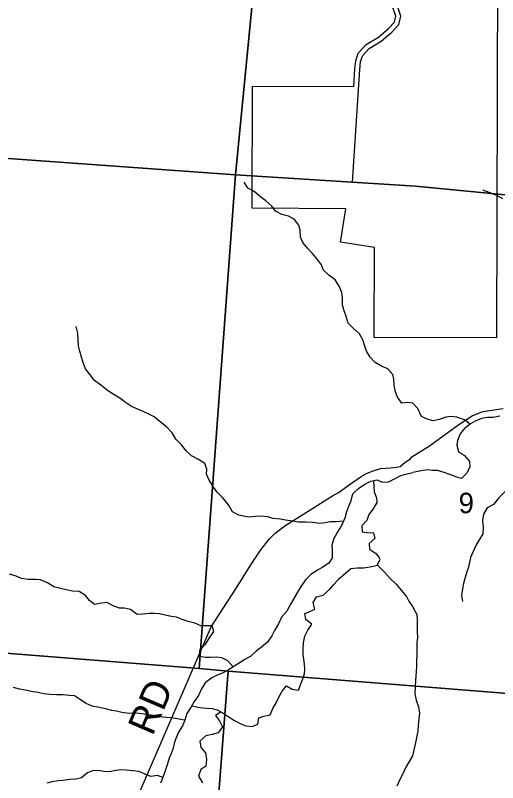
# Model space of a CAD drawing. Extents: x 0 to 34, y 0 to 22.
# Drawn here: x 27.839 to 28.825, y 17.514 to 19.082 of the extents above; entities that cross this region are included whole.
import ezdxf

# ---------------------------------------------------------------- set-up
doc = ezdxf.new("R2010")
doc.units = 0
for name, color, linetype in [('GM_X_City_Street', 7, 'Continuous'), ('GM_X_Corporation', 7, 'Continuous'), ('GM_X_County_Road', 7, 'Continuous'), ('GM_X_County_Road_Text', 7, 'Continuous'), ('GM_X_Minor_River', 7, 'Continuous'), ('GM_X_Section_Text', 7, 'Continuous')]:
    doc.layers.add(name, color=color, linetype=linetype)

msp = doc.modelspace()

# ---------------------------------------------------------------- linework, layer by layer
at = {"layer": 'GM_X_City_Street'}
msp.add_lwpolyline([(28.5283, 18.7412), (28.5427, 18.9719), (28.5446, 18.9871), (28.5485, 18.9999), (28.5622, 19.0147), (28.5869, 19.0297), (28.6086, 19.0482), (28.6227, 19.0634), (28.6265, 19.0804), (28.6183, 19.1051)], dxfattribs=at)
at = {"layer": 'GM_X_Corporation'}
for points in [[(27.4311, 19.8373), (28.3876, 19.7694), (28.2889, 18.7562), (27.2938, 18.8276), (27.3834, 19.8411)], [(28.4917, 19.7627), (29.3585, 19.6871), (29.2972, 18.6715), (28.6566, 18.7331), (28.2889, 18.7562), (28.3876, 19.7694)], [(27.2938, 18.8276), (28.2889, 18.7562), (28.2146, 17.7472), (27.2101, 17.8272)], [(28.2889, 18.7562), (28.6566, 18.7331), (29.2972, 18.6715), (29.263, 17.6631), (28.2741, 17.7417), (28.2146, 17.7472)], [(27.1442, 17.8319), (27.2101, 17.8272), (28.2146, 17.7472), (28.2741, 17.7417), (28.199, 16.7653), (27.1145, 16.8163), (27.1132, 17.3107)], [(28.2741, 17.7417), (29.263, 17.6631), (29.176, 16.6858), (28.199, 16.7653)]]:
    msp.add_lwpolyline(points, close=True, dxfattribs=at)
msp.add_lwpolyline([(28.8245, 19.173), (28.8221, 18.423), (28.5721, 18.4238), (28.5727, 18.6075), (28.5037, 18.6184), (28.5146, 18.6872), (28.3229, 18.6879), (28.3237, 18.9379), (28.5308, 18.9372), (28.533, 18.9733), (28.5351, 18.9896), (28.5398, 19.0053), (28.5559, 19.0226), (28.5811, 19.038), (28.6018, 19.0556), (28.6138, 19.0685), (28.6165, 19.0805), (28.6091, 19.1027)], dxfattribs=at)
at = {"layer": 'GM_X_County_Road'}
msp.add_lwpolyline([(27.9956, 17.2684), (28.2389, 17.8323), (28.2894, 17.91), (28.3217, 17.9615), (28.3409, 17.9902), (28.3576, 18.0116), (28.3691, 18.0235), (28.3899, 18.0387), (28.4873, 18.1004), (28.5005, 18.1078), (28.5191, 18.1217), (28.5457, 18.1395), (28.5577, 18.1469), (28.572, 18.1519), (28.5859, 18.1558), (28.6056, 18.1577), (28.618, 18.1588), (28.6257, 18.1604), (28.6354, 18.1689), (28.6457, 18.1754), (28.6492, 18.1803), (28.6854, 18.2027), (28.7455, 18.2461), (28.7723, 18.2641), (28.7943, 18.2729), (28.8356, 18.2786)], dxfattribs=at)
at = {"layer": 'GM_X_Minor_River'}
for points in [[(28.6514, 18.2895), (28.6404, 18.2907), (28.6291, 18.2896), (28.6201, 18.3022), (28.6152, 18.3151), (28.6134, 18.3269), (28.6124, 18.3387), (28.6102, 18.3485), (28.6004, 18.36), (28.5872, 18.3654), (28.5744, 18.3727), (28.5639, 18.3837), (28.5564, 18.3959), (28.5523, 18.4081), (28.549, 18.4191), (28.5426, 18.4317), (28.531, 18.4416), (28.5189, 18.4534), (28.5149, 18.4671), (28.51, 18.4804), (28.5078, 18.4899), (28.5076, 18.5043), (28.5061, 18.5161), (28.5005, 18.5287), (28.4927, 18.5416), (28.4799, 18.5516), (28.4682, 18.5619), (28.4645, 18.5725), (28.4566, 18.5836), (28.4461, 18.5958), (28.4364, 18.6065), (28.4262, 18.6183), (28.4217, 18.6289), (28.4211, 18.643), (28.4181, 18.6536), (28.4088, 18.6658), (28.3974, 18.672), (28.3835, 18.6755), (28.371, 18.682), (28.3631, 18.6923), (28.3511, 18.7034), (28.341, 18.7106), (28.327, 18.7225), (28.3138, 18.729), (28.3067, 18.7412)], [(28.8354, 18.7071), (28.8214, 18.7147), (28.8075, 18.7205), (28.7946, 18.7247)], [(28.5103, 18.0484), (28.495, 18.0474), (28.4825, 18.0471), (28.473, 18.0449), (28.4609, 18.0435), (28.4473, 18.0455), (28.4329, 18.0463), (28.4178, 18.0464), (28.4061, 18.0488), (28.3913, 18.0504), (28.3807, 18.0527), (28.3649, 18.054), (28.355, 18.0575), (28.3418, 18.0587), (28.3293, 18.058), (28.3157, 18.057), (28.3055, 18.0589), (28.2957, 18.0609), (28.2828, 18.0678), (28.2746, 18.0819), (28.2626, 18.0968), (28.251, 18.1086), (28.2435, 18.1196), (28.2348, 18.1322), (28.23, 18.1444), (28.2301, 18.1546), (28.2264, 18.1664), (28.2132, 18.1745), (28.1992, 18.1821), (28.1891, 18.1913), (28.1786, 18.2043), (28.1673, 18.2161), (28.1598, 18.2287), (28.1478, 18.2413), (28.135, 18.2516), (28.123, 18.2619), (28.112, 18.2673), (28.1, 18.2727), (28.0762, 18.2831), (28.0638, 18.2911), (28.0525, 18.2999), (28.0389, 18.3084), (28.0276, 18.3156), (28.014, 18.3264), (28.0005, 18.3363), (27.9896, 18.3504), (27.9825, 18.3599), (27.9773, 18.3729), (27.9743, 18.3839), (27.9706, 18.3961), (27.9684, 18.4067), (27.9674, 18.4196), (27.9667, 18.4325), (27.9634, 18.4462)], [(28.7683, 18.2468), (28.7567, 18.2557), (28.7415, 18.2611), (28.7287, 18.2622), (28.7185, 18.2608), (28.7052, 18.2566), (28.6927, 18.2533), (28.6806, 18.2567), (28.6689, 18.2621), (28.6617, 18.2791), (28.6514, 18.2895)], [(28.829, 18.2634), (28.8157, 18.2604), (28.804, 18.2605), (28.7919, 18.2582), (28.779, 18.253), (28.7695, 18.2477), (28.7562, 18.2375), (28.7482, 18.2273), (28.7425, 18.2133), (28.7413, 18.2038), (28.7447, 18.1909), (28.7568, 18.1825), (28.767, 18.1707), (28.7677, 18.1597), (28.7616, 18.1465), (28.751, 18.1359), (28.7411, 18.1386), (28.7268, 18.1439), (28.7154, 18.1481), (28.7014, 18.152), (28.6916, 18.152), (28.6818, 18.1532), (28.6719, 18.1521), (28.6511, 18.1477)], [(28.9456, 18.1756), (28.9327, 18.1713), (28.9259, 18.1577), (28.9164, 18.1543), (28.9073, 18.1433), (28.8955, 18.1346), (28.8872, 18.1248), (28.8739, 18.1207), (28.8603, 18.1166), (28.8493, 18.1117), (28.8387, 18.1075), (28.8261, 18.0954), (28.8159, 18.0826), (28.8034, 18.0754), (28.7957, 18.0629), (28.7934, 18.0497), (28.7949, 18.0356), (28.7941, 18.0227), (28.7872, 18.0102), (28.78, 17.9985), (28.7693, 17.9742)], [(28.4869, 17.9747), (28.487, 17.9902), (28.4867, 18.0004), (28.4906, 18.0137), (28.4963, 18.0235), (28.5028, 18.0341), (28.5086, 18.0443), (28.5132, 18.0553), (28.5167, 18.0685), (28.5206, 18.0791), (28.5244, 18.0889), (28.5287, 18.1045), (28.5401, 18.1154), (28.5534, 18.1244), (28.5652, 18.1304), (28.5781, 18.1333), (28.5886, 18.1283), (28.6019, 18.1286), (28.614, 18.135), (28.6269, 18.1417), (28.6372, 18.1447), (28.6511, 18.1477)], [(28.571, 18.1317), (28.5719, 18.1186), (28.5722, 18.1083), (28.5771, 18.0965), (28.5777, 18.0863), (28.5701, 18.0738), (28.5613, 18.0621), (28.5574, 18.05), (28.5468, 18.0387), (28.5478, 18.0266), (28.5576, 18.025), (28.5709, 18.0249), (28.5738, 18.0128), (28.5624, 18.003), (28.5627, 17.9912), (28.5751, 17.9828), (28.5825, 17.9745)], [(28.4869, 17.9747), (28.4795, 17.9627), (28.4658, 17.954), (28.4563, 17.948), (28.443, 17.9397), (28.432, 17.9284), (28.4233, 17.9159), (28.4157, 17.9034), (28.4081, 17.8905), (28.4008, 17.8777), (28.394, 17.8644), (28.383, 17.8524), (28.3769, 17.8387), (28.3685, 17.8251), (28.3631, 17.8141), (28.354, 17.8009), (28.3419, 17.7911), (28.332, 17.7832), (28.3202, 17.7726), (28.3081, 17.7658), (28.2982, 17.7594), (28.2854, 17.7511), (28.2759, 17.7455), (28.2626, 17.738), (28.2531, 17.7342), (28.2403, 17.7282), (28.227, 17.718), (28.2197, 17.7055), (28.2133, 17.6923), (28.2045, 17.6802), (28.1977, 17.6673), (28.1897, 17.6552), (28.1851, 17.642), (28.1805, 17.6302), (28.1725, 17.6174), (28.1668, 17.6041), (28.1633, 17.5943), (28.1618, 17.5848), (28.1584, 17.575), (28.1534, 17.5644), (28.1503, 17.5526), (28.1461, 17.5405), (28.1412, 17.5265), (28.1354, 17.5133)], [(28.1998, 17.6713), (28.2162, 17.6673), (28.2306, 17.6664), (28.2412, 17.6656), (28.2517, 17.6629), (28.2616, 17.6576), (28.274, 17.6492), (28.2872, 17.6412), (28.3001, 17.6343), (28.3099, 17.6301), (28.3227, 17.6289), (28.3345, 17.6334), (28.3364, 17.6463), (28.3466, 17.6497), (28.3595, 17.6527), (28.3652, 17.6659), (28.3725, 17.6788), (28.3774, 17.6886), (28.3843, 17.7007), (28.3934, 17.7121), (28.4047, 17.7048), (28.4176, 17.7029), (28.4222, 17.7161), (28.4264, 17.726), (28.4298, 17.7362), (28.4306, 17.746), (28.4299, 17.7559), (28.4288, 17.7661), (28.4273, 17.776), (28.4274, 17.787), (28.4278, 17.7999), (28.4305, 17.8131), (28.437, 17.8256), (28.4449, 17.8381), (28.4329, 17.8472), (28.4303, 17.8598), (28.4397, 17.8631), (28.4511, 17.8684), (28.4478, 17.8821), (28.4546, 17.8938), (28.4679, 17.8971), (28.4819, 17.9092), (28.4903, 17.9194), (28.5005, 17.9311), (28.5134, 17.9421), (28.5244, 17.9515), (28.5377, 17.953), (28.5505, 17.9529), (28.5642, 17.9552), (28.5782, 17.9585), (28.5846, 17.9702), (28.5825, 17.9745)], [(28.7693, 17.9742), (28.7652, 17.9548), (28.7614, 17.9446), (28.7583, 17.9336), (28.7552, 17.9211), (28.7525, 17.9105), (28.751, 17.8965), (28.7528, 17.8844)], [(28.5784, 17.959), (28.594, 17.9437), (28.6053, 17.9311), (28.6174, 17.9197), (28.6275, 17.9075), (28.6381, 17.8946), (28.6433, 17.8851), (28.6508, 17.874)], [(28.2844, 17.7506), (28.2733, 17.7633), (28.2612, 17.7694), (28.2491, 17.7702), (28.2381, 17.7695), (28.2279, 17.7699), (28.2151, 17.7719), (28.2163, 17.7851), (28.2273, 17.7972), (28.2356, 17.8097), (28.2444, 17.8229), (28.241, 17.8347), (28.2183, 17.8348), (28.2055, 17.8402), (28.1923, 17.8432), (28.1802, 17.8478), (28.1685, 17.852), (28.1579, 17.8536), (28.1477, 17.8559), (28.1337, 17.859), (28.1231, 17.8598), (28.1125, 17.8595), (28.0989, 17.8584), (28.0879, 17.858), (28.0743, 17.8679), (28.0618, 17.871), (28.0516, 17.8707), (28.0388, 17.8757), (28.0263, 17.8825), (28.0112, 17.8799), (28.0006, 17.8785), (27.9908, 17.8861), (27.9825, 17.8967), (27.9693, 17.9044), (27.956, 17.9056), (27.9428, 17.9083), (27.9311, 17.9106), (27.9175, 17.9144), (27.905, 17.9224), (27.8903, 17.9285), (27.8801, 17.9293), (27.865, 17.9294), (27.8514, 17.9314), (27.8408, 17.9363), (27.8272, 17.9402)], [(28.6508, 17.874), (28.6597, 17.8575), (28.6604, 17.8473), (28.6604, 17.8332), (28.6599, 17.8238), (28.6606, 17.8101), (28.6598, 17.8003), (28.6598, 17.7859), (28.6593, 17.7745), (28.6585, 17.7646), (28.6585, 17.7518), (28.6581, 17.7415), (28.6573, 17.732), (28.6569, 17.7226), (28.6564, 17.7093), (28.6556, 17.6953), (28.6582, 17.6824), (28.663, 17.6687), (28.6649, 17.6562), (28.6637, 17.6441), (28.6621, 17.6316), (28.6613, 17.6191), (28.659, 17.6054), (28.6563, 17.5925), (28.6503, 17.5689)], [(28.185, 17.6418), (28.1696, 17.6447), (28.1579, 17.6466), (28.1473, 17.647), (28.1333, 17.6486), (28.1208, 17.6513), (28.1072, 17.6536), (28.0921, 17.6552), (28.0819, 17.656), (28.0713, 17.6557), (28.0565, 17.6576), (28.0459, 17.6599), (28.0361, 17.6615), (28.0236, 17.6646), (28.01, 17.6677), (27.9957, 17.6704), (27.984, 17.6761), (27.9722, 17.6834), (27.9602, 17.6914), (27.95, 17.6925), (27.9363, 17.6937), (27.9231, 17.6938), (27.9099, 17.6942), (27.8974, 17.6958), (27.8857, 17.6981), (27.8755, 17.6996), (27.8588, 17.7031), (27.8475, 17.7054), (27.835, 17.7085)], [(28.2594, 17.6588), (28.2483, 17.6512), (28.2562, 17.6402), (28.2626, 17.628), (28.2538, 17.6159), (28.241, 17.6126), (28.2281, 17.6096), (28.2159, 17.599), (28.2178, 17.5861), (28.2276, 17.5747), (28.2294, 17.5614), (28.2286, 17.5478), (28.218, 17.5406), (28.213, 17.527), (28.2213, 17.5137)], [(28.6503, 17.5689), (28.6372, 17.5455), (28.6318, 17.5334), (28.625, 17.5205), (28.6189, 17.5069)], [(28.1403, 17.5245), (28.1298, 17.5285), (28.1158, 17.5266), (28.1056, 17.5308), (28.0924, 17.5366), (28.0788, 17.5381), (28.0655, 17.5393), (28.0546, 17.5405), (28.0447, 17.539), (28.0315, 17.536), (28.0201, 17.5365), (28.008, 17.5392), (27.9967, 17.5385), (27.9868, 17.5339), (27.9743, 17.5241), (27.9626, 17.5215), (27.9505, 17.5204), (27.9361, 17.5182), (27.9262, 17.5179), (27.9138, 17.516), (27.9031, 17.5127)]]:
    msp.add_lwpolyline(points, dxfattribs=at)

# ---------------------------------------------------------------- texts
at = {"layer": 'GM_X_County_Road_Text'}
msp.add_text('RD', height=0.05682, rotation=66.7366, dxfattribs=at).set_placement((28.1193, 17.6078))
at = {"layer": 'GM_X_Section_Text'}
msp.add_text('9', height=0.0419, rotation=0, dxfattribs=at).set_placement((28.745, 18.0647))

doc.saveas('drawing.dxf')
